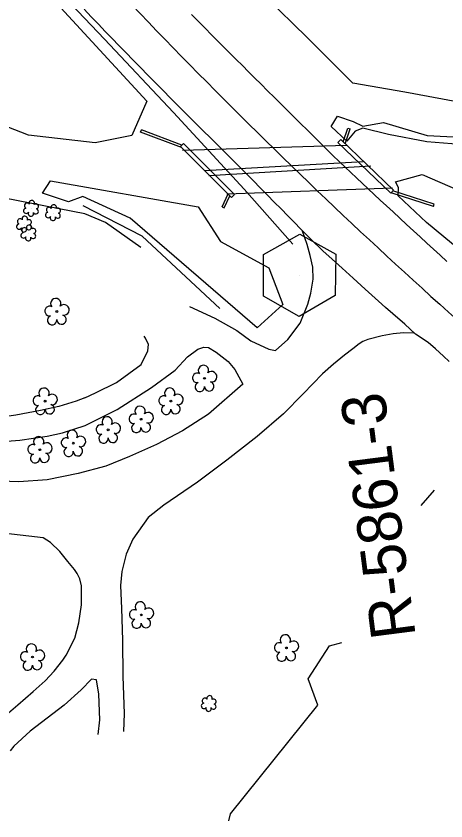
# Model space of a CAD drawing. Extents: x 477009 to 479892, y 492858 to 496862.
# Drawn here: x 478930.8 to 479085.5, y 493762.2 to 494052.3 of the extents above; entities that cross this region are included whole.
import ezdxf

# ---------------------------------------------------------------- set-up
doc = ezdxf.new("R2010")
doc.units = 0
for name, color, linetype in [('CTL Primary Horizontal and Vertical CELL', 7, 'Continuous'), ('CTL Primary Horizontal and Vertical Text', 7, 'Continuous'), ('Exist Guardrail', 7, 'Continuous'), ('Exist Horizontal Alignment', 7, 'Continuous'), ('Exist Other Culture Fence Line', 7, 'Continuous'), ('Exist Other Culture Sign', 7, 'Continuous'), ('Exist Roads EOP', 7, 'Continuous'), ('Exist Roads Soil', 7, 'Continuous'), ('Exist Structure Major Box Culvert or Tunnel Topo', 7, 'Continuous'), ('Exist Structure Major Bridge WW', 7, 'Continuous'), ('Exist Structure Minor Head and End Wall', 7, 'Continuous'), ('Exist Vegetation Hedge Row', 7, 'Continuous'), ('Exist Vegetation Shrub CELL', 7, 'Continuous'), ('Exist Vegetation Tree CELL', 7, 'Continuous'), ('Exist Vegetation Woods Line', 7, 'Continuous')]:
    doc.layers.add(name, color=color, linetype=linetype)

msp = doc.modelspace()

# ---------------------------------------------------------------- linework, layer by layer
at = {"layer": 'CTL Primary Horizontal and Vertical CELL'}
msp.add_line((479032.82, 493958.97), (479032.82, 493958.97), dxfattribs=at)
msp.add_lwpolyline([(479019.89, 493966.46), (479032.89, 493973.71), (479045.89, 493966.56), (479045.69, 493951.66), (479032.69, 493944.11), (479019.89, 493951.36)], close=True, dxfattribs=at)
at = {"layer": 'Exist Guardrail'}
msp.add_lwpolyline([(479030.35, 493970.18), (479012.92, 493989.95), (478987.43, 494017.59), (478962.55, 494044.08), (478941.05, 494066.79), (478920.73, 494088.95), (478898.6, 494113.95), (478881.42, 494133.89), (478865.31, 494153.16), (478848.96, 494173.09)], dxfattribs=at)
at = {"layer": 'Exist Horizontal Alignment'}
msp.add_arc((480415.92, 495427.95), 1991.17, 222.54643, 230.46528, dxfattribs=at)
at = {"layer": 'Exist Other Culture Fence Line'}
for points in [[(479108.16, 494017.94), (479070.79, 494024.96), (479052.06, 494028.2), (479035.55, 494044.67), (479005.51, 494074.07), (478956.05, 494123.48), (478945.66, 494161.44), (478974.21, 494187.61), (479002.57, 494213.48)], [(478975.72, 493968.99), (478962.89, 493977.98), (478955.55, 493981.1), (478906.78, 493990.56)], [(479004.13, 493947), (478976.17, 493972.97), (478954.95, 493983.97)]]:
    msp.add_lwpolyline(points, dxfattribs=at)
at = {"layer": 'Exist Other Culture Sign'}
msp.add_line((479081.28, 493881.44), (479076.52, 493875.94), dxfattribs=at)
at = {"layer": 'Exist Roads EOP'}
for points in [[(479086.73, 493927.88), (479084.65, 493929.72), (479081.75, 493932.37), (479079.12, 493934.69), (479074.63, 493937.71), (479070.68, 493941.32), (479066.4, 493945.06), (479063.79, 493947.33), (479061.26, 493949.56), (479058.82, 493951.74), (479056.47, 493953.87), (479052.08, 493957.9), (479048.13, 493961.52), (479044.55, 493964.78), (479041.26, 493967.75), (479036.97, 493971.77), (479033.17, 493975.67), (479030.99, 493977.89), (479028.57, 493980.35), (479026.16, 493982.82), (479023.74, 493985.29), (479021.32, 493987.78), (479018.81, 493990.35), (479016.13, 493993.07), (479013.27, 493995.95), (479010.24, 493998.98), (479007.13, 494002.08), (479004.03, 494005.16), (479000.94, 494008.23), (478997.87, 494011.27), (478994.84, 494014.26), (478991.91, 494017.18), (478989.08, 494020.03), (478986.35, 494022.8), (478983.66, 494025.53), (478980.96, 494028.28), (478978.25, 494031.03), (478975.54, 494033.78), (478972.86, 494036.51), (478970.26, 494039.16), (478967.75, 494041.74), (478965.31, 494044.25), (478962.88, 494046.77), (478960.38, 494049.38), (478957.83, 494052.08), (478955.21, 494054.87)], [(479085.82, 493963.88), (479083.41, 493966.11), (479081.01, 493968.33), (479078.62, 493970.53), (479076.22, 493972.74), (479073.8, 493974.97), (479071.36, 493977.22), (479068.91, 493979.5), (479066.48, 493981.75), (479064.13, 493983.93), (479061.86, 493986.04), (479057.51, 493990.08), (479053.32, 493994), (479049.21, 493997.89), (479047.06, 493999.95), (479044.83, 494002.13), (479042.51, 494004.41), (479040.16, 494006.73), (479037.84, 494009.02), (479035.54, 494011.3), (479033.26, 494013.55), (479030.97, 494015.83), (479028.62, 494018.16), (479026.22, 494020.54), (479023.77, 494022.99), (479021.33, 494025.43), (479018.96, 494027.8), (479016.66, 494030.09), (479014.43, 494032.31), (479012.24, 494034.5), (479010.05, 494036.69), (479007.85, 494038.88), (479005.66, 494041.08), (479003.43, 494043.32), (479001.14, 494045.63), (478998.78, 494048.03), (478996.35, 494050.5), (478993.96, 494052.94)]]:
    msp.add_lwpolyline(points, dxfattribs=at)
at = {"layer": 'Exist Roads Soil'}
msp.add_line((478955.48, 493914.73), (478952.38, 493913.59), dxfattribs=at)
for points in [[(478993.14, 493947.69), (479002.3, 493943.43), (479010.19, 493939.01), (479015.31, 493935.25), (479021.75, 493932.23), (479024.18, 493931.83), (479028.62, 493935.81), (479033, 493941.6), (479035.86, 493948.56), (479036.91, 493952.44), (479037.73, 493957.49), (479037.56, 493961.86), (479036.62, 493966.03), (479035.53, 493970.05), (479033.83, 493974.83)], [(479073.87, 493938.07), (479070.2, 493938.16), (479066.48, 493937.85), (479062.57, 493937.05), (479057.46, 493935.72), (479055.65, 493935)], [(478955.48, 493914.73), (478959.36, 493916.5), (478966.92, 493920.33), (478975.74, 493926.72), (478978.17, 493931.74), (478978.43, 493933.92), (478977.38, 493936.23), (478976.88, 493936.96)], [(479055.65, 493935), (479054.28, 493934.17), (479052.07, 493932.38), (479049.07, 493930.12), (479045.02, 493926.86), (479041.1, 493923.35), (479034.13, 493916.24), (479027.03, 493908.98), (479017.55, 493900.84), (479006.68, 493892.22), (478996.02, 493884.31), (478983.92, 493876.1), (478978.27, 493871.62), (478972.82, 493863.83), (478970.44, 493858.45), (478968.87, 493852.12), (478968.38, 493847.07), (478968.65, 493838.84), (478969.07, 493827.36), (478969.2, 493814.25), (478969.72, 493800.96), (478969.43, 493794.44)], [(478924.35, 493898.89), (478932.14, 493899.43), (478941.95, 493900.97), (478947.51, 493902.12), (478955.61, 493904.83), (478967.17, 493910.49), (478979.53, 493918.48), (478988.03, 493924.77), (478992.46, 493929.51), (478996.21, 493932.27), (478998.35, 493933.03), (479000.03, 493932.94), (479002.74, 493931.21), (479007.09, 493927.78), (479009.47, 493924.9), (479012.35, 493919.64)], [(479012.35, 493919.64), (478999.99, 493908.91), (478990.62, 493902.82), (478981.32, 493897.95), (478971.58, 493893.63), (478963.12, 493890.15), (478953.1, 493887.49), (478941.98, 493885.23), (478931.69, 493884.43), (478925.2, 493884.74)], [(478952.38, 493913.59), (478946.17, 493911.59), (478939.52, 493910.21), (478930.62, 493908.55), (478923.01, 493907.47), (478922.79, 493913.1), (478918.38, 493913.34)], [(478925.53, 493799.05), (478931.37, 493804.03), (478936.87, 493808.9), (478941.18, 493812.75), (478944.42, 493816.19), (478947.53, 493820.24), (478948.84, 493822.04), (478951.9, 493828.09), (478953.33, 493833.59), (478954.25, 493840.08), (478954.32, 493844.24), (478954.3, 493846.97), (478953.7, 493849.51), (478952.8, 493851.38), (478951.73, 493852.82), (478949.35, 493855.73), (478946.52, 493859.32), (478943.19, 493862.64), (478940.56, 493864.31), (478927.06, 493865.9)], [(478960.31, 493793.34), (478960.89, 493798.64), (478960.52, 493807.94), (478959.68, 493813.07), (478957.9, 493813.28), (478954.13, 493809.5), (478948.05, 493803.97), (478935.78, 493794.57), (478929.99, 493789.19), (478928.63, 493787.56)]]:
    msp.add_lwpolyline(points, dxfattribs=at)
at = {"layer": 'Exist Structure Major Box Culvert or Tunnel Topo'}
for p, q in [((478990.66, 494003.99), (479049.69, 494005.81)), ((478998.62, 493996.7), (479055.77, 493999.96)), ((479058.53, 493998.3), (479000.15, 493994.78)), ((479006.62, 493988.22), (479066.33, 493990.38))]:
    msp.add_line(p, q, dxfattribs=at)
at = {"layer": 'Exist Structure Major Bridge WW'}
for p, q in [((478990.35, 494004.95), (478975.6, 494010.52)), ((478990.45, 494005.8), (478975.89, 494011.3)), ((479048.54, 494006.97), (479050.24, 494011.93)), ((479049.2, 494006.33), (479051.02, 494011.66)), ((479004.94, 493983.6), (479007.11, 493988.24)), ((479005.69, 493983.25), (479007.73, 493987.61)), ((479081.09, 493983.76), (479065.77, 493988.66)), ((479081.35, 493984.55), (479066.41, 493989.33))]:
    msp.add_line(p, q, dxfattribs=at)
at = {"layer": 'Exist Structure Minor Head and End Wall'}
for p, q in [((478975.6, 494010.52), (478975.89, 494011.3)), ((479050.24, 494011.93), (479051.02, 494011.66)), ((479046.62, 494006.72), (479047.65, 494007.81)), ((479066.71, 493989.64), (479047.65, 494007.81)), ((478989.98, 494005.32), (478991.04, 494006.38)), ((479008.34, 493987), (478989.98, 494005.32)), ((479009.4, 493988.06), (478991.04, 494006.38)), ((479065.67, 493988.55), (479046.62, 494006.72)), ((479065.67, 493988.55), (479066.71, 493989.64)), ((479008.34, 493987), (479009.4, 493988.06)), ((479004.94, 493983.6), (479005.69, 493983.25)), ((479081.09, 493983.76), (479081.35, 493984.55))]:
    msp.add_line(p, q, dxfattribs=at)
at = {"layer": 'Exist Vegetation Hedge Row'}
for points in [[(478845.51, 494172.66), (478883.99, 494125.4), (478918.58, 494086.08), (478977.87, 494021.65), (478972.39, 494009.31), (478959.23, 494006.7), (478935.26, 494009.43), (478912.01, 494018.49), (478896.29, 494022.75), (478906.04, 494052.55), (478906.48, 494061.88), (478899.05, 494070.85), (478890.35, 494076.64), (478878.48, 494092.19)], [(479096.63, 494005.63), (479078.72, 494007.07), (479064.9, 494009.62), (479055.61, 494011.94), (479052.88, 494010.84), (479049.89, 494007.25), (479044.21, 494012.52), (479046.53, 494016.23), (479052.16, 494014.3), (479055.59, 494012.7), (479063, 494013.98), (479078.8, 494009.34), (479092.9, 494008.55)], [(479078.52, 493977.98), (479068.39, 493987.61), (479068.42, 493990.58), (479067.35, 493992.62), (479076.93, 493995.26), (479089.7, 493989.76)], [(478943.11, 493992.92), (478996.29, 493983.55), (479004.31, 493971.12), (479021.82, 493961.58), (479026.76, 493948.38), (479017.52, 493939.98), (478971.78, 493979.49), (478954.8, 493987.35), (478949.6, 493985.35), (478940.27, 493988.57), (478943.11, 493992.92)], [(479202.84, 493937.4), (479192.99, 493940.45), (479170.55, 493961.53), (479159.94, 493965.4), (479157.61, 493955.73), (479164.16, 493946.19), (479154.57, 493939.38), (479135.06, 493949.04), (479124.4, 493942.25), (479097.29, 493962.49), (479078.52, 493977.98)]]:
    msp.add_lwpolyline(points, dxfattribs=at)
at = {"layer": 'Exist Vegetation Shrub CELL'}
for p, q in [((478936.2, 493982.87), (478936.2, 493982.87)), ((478944.1, 493981.33), (478944.1, 493981.33)), ((478933.68, 493977.19), (478933.68, 493977.19)), ((478935.24, 493974.01), (478935.24, 493974.01)), ((479000.2, 493804.39), (479000.2, 493804.39))]:
    msp.add_line(p, q, dxfattribs=at)
for centre, radius, start, end in [((478934.71, 493984), 0.968, 35.8908, 245.4216), ((478936.42, 493984.91), 0.99, 334.8391, 200.4717), ((478937.87, 493983.74), 0.929, 284.4567, 126.0861), ((478944.33, 493983.37), 0.99, 334.8391, 200.4717), ((478934.4, 493982.17), 0.955, 95.1099, 327.9534), ((478936.07, 493981.19), 0.984, 151.2797, 21.387), ((478937.83, 493981.94), 0.937, 204.9913, 73.4601), ((478942.3, 493980.63), 0.955, 95.1099, 327.9534), ((478942.62, 493982.46), 0.968, 35.8908, 245.4216), ((478945.74, 493980.4), 0.937, 204.9913, 73.4601), ((478945.77, 493982.2), 0.929, 284.4567, 126.0861), ((478932.2, 493978.31), 0.968, 35.8908, 245.4216), ((478933.91, 493979.23), 0.99, 334.8391, 200.4717), ((478935.36, 493978.06), 0.929, 284.4567, 126.0861), ((478943.97, 493979.65), 0.984, 151.2797, 21.387), ((478931.88, 493976.48), 0.955, 95.1099, 327.9534), ((478933.56, 493975.5), 0.984, 151.2797, 21.387), ((478933.76, 493975.13), 0.968, 35.8908, 245.4216), ((478935.32, 493976.26), 0.937, 204.9913, 73.4601), ((478935.47, 493976.05), 0.99, 334.8391, 200.4717), ((478936.91, 493974.87), 0.929, 284.4567, 126.0861), ((478933.44, 493973.3), 0.955, 95.1099, 327.9534), ((478935.11, 493972.32), 0.984, 151.2797, 21.387), ((478936.88, 493973.08), 0.937, 204.9913, 73.4601), ((479000.43, 493806.43), 0.99, 334.8391, 200.4717), ((478998.4, 493803.68), 0.955, 95.1099, 327.9534), ((478998.72, 493805.52), 0.968, 35.8908, 245.4216), ((479001.84, 493803.46), 0.937, 204.9913, 73.4601), ((479001.87, 493805.26), 0.929, 284.4567, 126.0861), ((479000.07, 493802.71), 0.984, 151.2797, 21.387)]:
    msp.add_arc(centre, radius, start, end, dxfattribs=at)
at = {"layer": 'Exist Vegetation Tree CELL'}
for p, q in [((478945.43, 493945.86), (478945.43, 493945.86)), ((478998.62, 493921.77), (478998.62, 493921.77)), ((478941.18, 493913.56), (478941.18, 493913.56)), ((478986.5, 493913.57), (478986.5, 493913.57)), ((478975.76, 493907.01), (478975.76, 493907.01)), ((478963.93, 493903.21), (478963.93, 493903.21)), ((478951.36, 493898.42), (478951.36, 493898.42)), ((478939.3, 493896.04), (478939.3, 493896.04)), ((478975.85, 493836.49), (478975.85, 493836.49)), ((479028.08, 493824.6), (479028.08, 493824.6)), ((478936.64, 493821.32), (478936.64, 493821.32))]:
    msp.add_line(p, q, dxfattribs=at)
for centre in [(478945.43, 493945.86), (478998.62, 493921.77), (478941.18, 493913.56), (478986.5, 493913.57), (478975.76, 493907.01), (478963.93, 493903.21), (478951.36, 493898.42), (478939.3, 493896.04), (478975.85, 493836.49), (479028.08, 493824.6), (478936.64, 493821.32)]:
    msp.add_circle(centre, 0.326, dxfattribs=at)
for centre, radius, start, end in [((478945.05, 493948.74), 1.86, 330.1651, 219.7134), ((478942.83, 493946.02), 1.73, 62.6636, 279.3457), ((478947.98, 493946.45), 1.9, 257.1011, 134.1999), ((478943.73, 493942.74), 1.69, 111.5671, 6.231), ((478947.1, 493942.96), 1.7, 181.2822, 74.56), ((478998.23, 493924.64), 1.86, 330.1651, 219.7134), ((478996.01, 493921.92), 1.73, 62.6636, 279.3457), ((479001.16, 493922.36), 1.9, 257.1011, 134.1999), ((478996.91, 493918.65), 1.69, 111.5671, 6.231), ((479000.29, 493918.87), 1.7, 181.2822, 74.56), ((478940.79, 493916.43), 1.86, 330.1651, 219.7134), ((478986.11, 493916.45), 1.86, 330.1651, 219.7134), ((478938.57, 493913.71), 1.73, 62.6636, 279.3457), ((478943.72, 493914.15), 1.9, 257.1011, 134.1999), ((478983.89, 493913.73), 1.73, 62.6636, 279.3457), ((478989.04, 493914.16), 1.9, 257.1011, 134.1999), ((478939.47, 493910.44), 1.69, 111.5671, 6.231), ((478942.85, 493910.66), 1.7, 181.2822, 74.56), ((478975.37, 493909.88), 1.86, 330.1651, 219.7134), ((478984.79, 493910.45), 1.69, 111.5671, 6.231), ((478988.17, 493910.67), 1.7, 181.2822, 74.56), ((478973.15, 493907.16), 1.73, 62.6636, 279.3457), ((478978.31, 493907.59), 1.9, 257.1011, 134.1999), ((478963.55, 493906.08), 1.86, 330.1651, 219.7134), ((478966.48, 493903.79), 1.9, 257.1011, 134.1999), ((478974.05, 493903.89), 1.69, 111.5671, 6.231), ((478977.43, 493904.11), 1.7, 181.2822, 74.56), ((478950.97, 493901.29), 1.86, 330.1651, 219.7134), ((478961.33, 493903.36), 1.73, 62.6636, 279.3457), ((478938.92, 493898.91), 1.86, 330.1651, 219.7134), ((478948.75, 493898.58), 1.73, 62.6636, 279.3457), ((478953.91, 493899.01), 1.9, 257.1011, 134.1999), ((478962.23, 493900.09), 1.69, 111.5671, 6.231), ((478965.61, 493900.31), 1.7, 181.2822, 74.56), ((478936.7, 493896.19), 1.73, 62.6636, 279.3457), ((478941.85, 493896.63), 1.9, 257.1011, 134.1999), ((478949.65, 493895.3), 1.69, 111.5671, 6.231), ((478953.03, 493895.52), 1.7, 181.2822, 74.56), ((478937.6, 493892.92), 1.69, 111.5671, 6.231), ((478940.98, 493893.14), 1.7, 181.2822, 74.56), ((478975.46, 493839.37), 1.86, 330.1651, 219.7134), ((478978.4, 493837.08), 1.9, 257.1011, 134.1999), ((478973.24, 493836.65), 1.73, 62.6636, 279.3457), ((478974.15, 493833.37), 1.69, 111.5671, 6.231), ((478977.52, 493833.59), 1.7, 181.2822, 74.56), ((479027.69, 493827.47), 1.86, 330.1651, 219.7134), ((479030.63, 493825.19), 1.9, 257.1011, 134.1999), ((478936.25, 493824.19), 1.86, 330.1651, 219.7134), ((479025.47, 493824.75), 1.73, 62.6636, 279.3457), ((478934.03, 493821.47), 1.73, 62.6636, 279.3457), ((478939.19, 493821.91), 1.9, 257.1011, 134.1999), ((479026.37, 493821.48), 1.69, 111.5671, 6.231), ((479029.75, 493821.7), 1.7, 181.2822, 74.56), ((478934.94, 493818.2), 1.69, 111.5671, 6.231), ((478938.31, 493818.42), 1.7, 181.2822, 74.56)]:
    msp.add_arc(centre, radius, start, end, dxfattribs=at)
at = {"layer": 'Exist Vegetation Woods Line'}
msp.add_lwpolyline([(479007.4, 493762.25), (479008, 493764.75), (479039.46, 493803.93), (479035.95, 493813.51), (479043.62, 493825.33), (479048, 493826.52)], dxfattribs=at)

# ---------------------------------------------------------------- texts
at = {"layer": 'CTL Primary Horizontal and Vertical Text'}
msp.add_text('R-5861-3', height=16, rotation=97.3349, dxfattribs=at).set_placement((479074.69, 493828.91))

doc.saveas('drawing.dxf')
